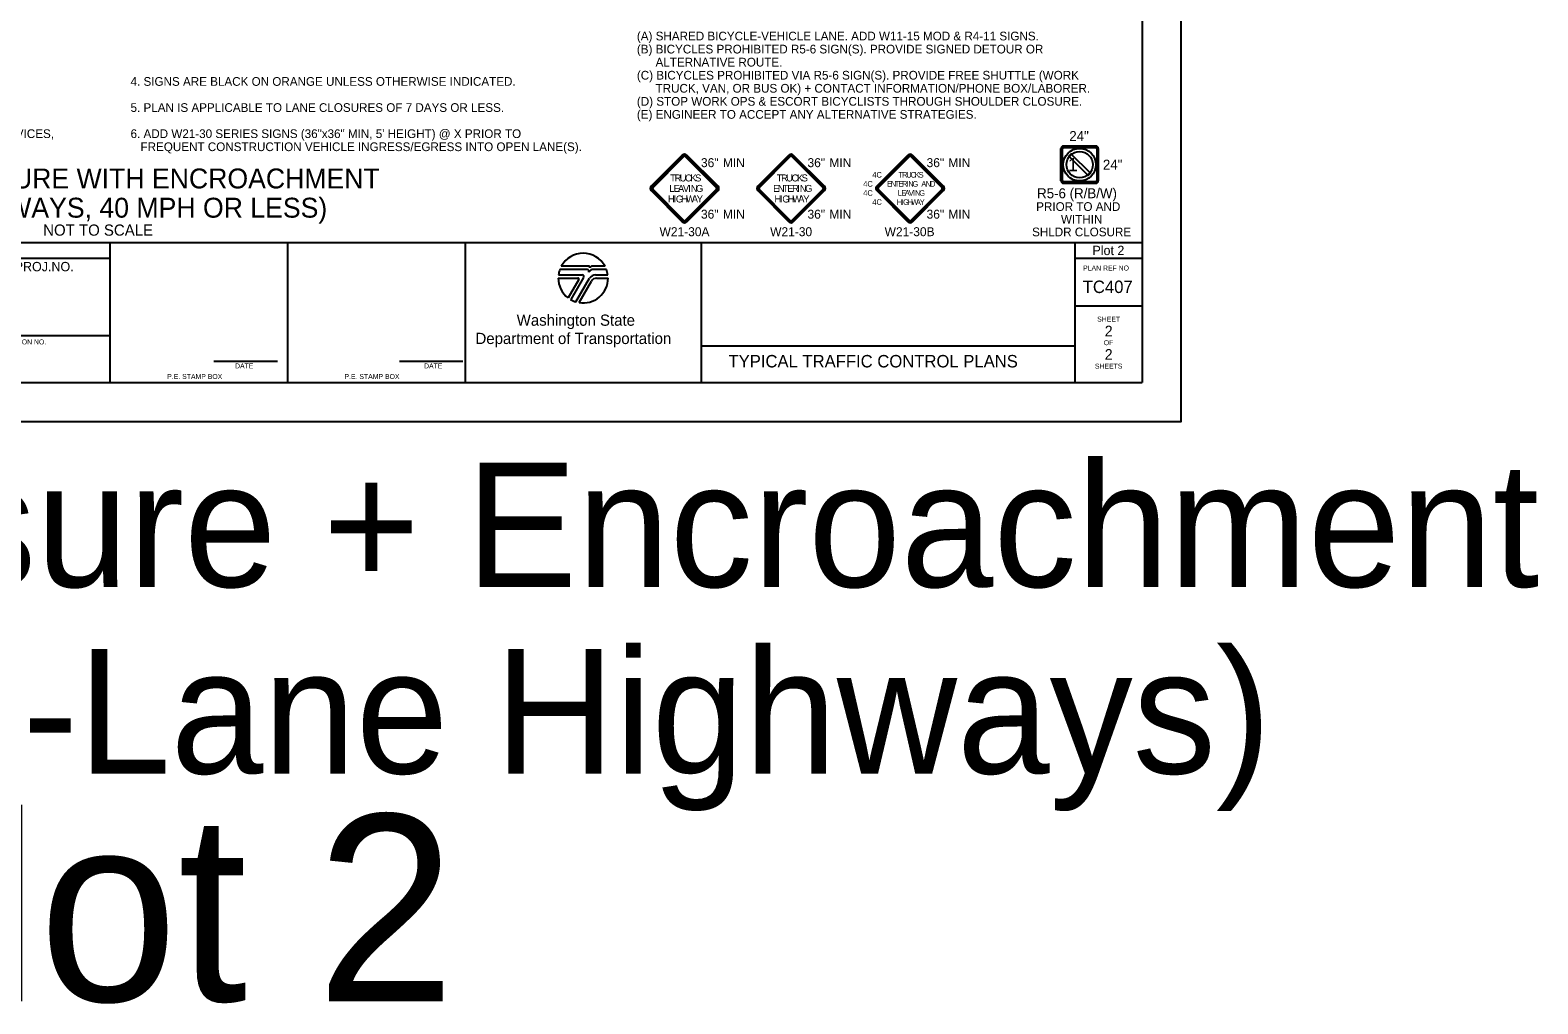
# Model space of a CAD drawing. Extents: x 99999.1 to 100096.1, y 99995 to 100010.7.
# Drawn here: x 100026.81 to 100038.93, y 99995.01 to 100002.83 of the extents above; entities that cross this region are included whole.
import ezdxf

# ---------------------------------------------------------------- set-up
doc = ezdxf.new("R2010")
doc.units = 0
for name, color, linetype in [('SH_DE_DetailHeading1Text', 7, 'Continuous'), ('SH_GI_GeneralNotesBodyText', 7, 'Continuous'), ('SH_GI_PlotLimits', 7, 'Continuous'), ('SH_GI_SheetBorder', 7, 'Continuous'), ('SH_GI_SheetLocationText', 7, 'Continuous'), ('SH_GI_SheetTextInCells', 7, 'Continuous'), ('SH_GI_TitleBlockText', 7, 'Continuous'), ('SH_GI_WSDOTLogo', 7, 'Continuous'), ('TR_SN_ConstructionSigns', 7, 'Continuous')]:
    doc.layers.add(name, color=color, linetype=linetype)

msp = doc.modelspace()

# ---------------------------------------------------------------- linework, layer by layer
at = {"layer": 'SH_GI_PlotLimits'}
msp.add_lwpolyline([(100019.062, 99999.687), (100036.062, 99999.687), (100036.062, 100010.687), (100019.062, 100010.687)], close=True, dxfattribs=at)
at = {"layer": 'SH_GI_SheetBorder'}
for p, q in [((100035.75, 100010.375), (100035.75, 100000)), ((100020, 100001.126), (100035.75, 100001.126)), ((100027.457, 100000), (100027.457, 100001.126)), ((100028.883, 100000), (100028.883, 100001.126)), ((100030.309, 100001.126), (100030.309, 100000)), ((100032.205, 100001.126), (100032.205, 100000)), ((100035.208, 100001.126), (100035.208, 100000)), ((100020, 100001.001), (100027.457, 100001.001)), ((100035.208, 100001.001), (100035.75, 100001.001)), ((100035.208, 100000.618), (100035.75, 100000.618)), ((100027.457, 100000.375), (100025.447, 100000.375)), ((100032.205, 100000.295), (100035.208, 100000.295)), ((100028.29, 100000.173), (100028.802, 100000.173)), ((100029.78, 100000.173), (100030.291, 100000.173)), ((100020, 100000), (100035.75, 100000))]:
    msp.add_line(p, q, dxfattribs=at)
at = {"layer": 'SH_GI_WSDOTLogo'}
for p, q in [((100031.303, 100000.935), (100031.081, 100000.935)), ((100031.433, 100000.935), (100031.335, 100000.935)), ((100031.057, 100000.84), (100031.215, 100000.84)), ((100031.059, 100000.866), (100031.25, 100000.866)), ((100031.289, 100000.909), (100031.07, 100000.909)), ((100031.222, 100000.828), (100031.136, 100000.681)), ((100031.261, 100000.846), (100031.157, 100000.667)), ((100031.199, 100000.649), (100031.309, 100000.839)), ((100031.224, 100000.643), (100031.324, 100000.816)), ((100031.445, 100000.909), (100031.343, 100000.909)), ((100031.343, 100000.909), (100031.343, 100000.909)), ((100031.356, 100000.866), (100031.456, 100000.866)), ((100031.365, 100000.839), (100031.457, 100000.839))]:
    msp.add_line(p, q, dxfattribs=at)
for centre, radius, start, end in [((100031.257, 100000.84), 0.2, 28.4787, 151.532), ((100031.303, 100000.926), 0.00903, 329.8742, 90.0033), ((100031.335, 100000.907), 0.0287, 90.0072, 148.1676), ((100031.257, 100000.84), 0.2, 179.9986, 232.8433), ((100031.257, 100000.84), 0.2, 159.696, 172.5057), ((100031.215, 100000.832), 0.0082, 329.7436, 90), ((100031.257, 100000.84), 0.2, 260.5455, 359.8086), ((100031.25, 100000.853), 0.0131, 329.7683, 90), ((100031.289, 100000.895), 0.0148, 327.8418, 89.9985), ((100031.343, 100000.861), 0.0484, 89.9953, 147.8238), ((100031.356, 100000.812), 0.0542, 90, 149.9974), ((100031.365, 100000.792), 0.0476, 90, 150.0543), ((100031.257, 100000.84), 0.2, 7.4943, 20.2941), ((100031.257, 100000.84), 0.2, 239.7929, 253.0448)]:
    msp.add_arc(centre, radius, start, end, dxfattribs=at)
at = {"layer": 'TR_SN_ConstructionSigns'}
for p, q in [((100032.054, 100001.829), (100031.804, 100001.579)), ((100032.059, 100001.824), (100031.809, 100001.574)), ((100031.816, 100001.567), (100032.066, 100001.817)), ((100032.078, 100001.817), (100032.329, 100001.567)), ((100032.336, 100001.574), (100032.085, 100001.824)), ((100032.341, 100001.579), (100032.09, 100001.829)), ((100032.91, 100001.829), (100032.66, 100001.579)), ((100032.915, 100001.824), (100032.665, 100001.574)), ((100032.672, 100001.567), (100032.922, 100001.817)), ((100032.934, 100001.817), (100033.185, 100001.567)), ((100033.192, 100001.574), (100032.941, 100001.824)), ((100033.197, 100001.579), (100032.946, 100001.829)), ((100033.867, 100001.829), (100033.616, 100001.579)), ((100033.872, 100001.824), (100033.621, 100001.574)), ((100033.628, 100001.567), (100033.879, 100001.817)), ((100033.891, 100001.817), (100034.141, 100001.567)), ((100034.148, 100001.574), (100033.898, 100001.824)), ((100034.153, 100001.579), (100033.903, 100001.829)), ((100035.097, 100001.883), (100035.097, 100001.621)), ((100035.097, 100001.621), (100035.097, 100001.883)), ((100035.097, 100001.883), (100035.097, 100001.621)), ((100035.102, 100001.883), (100035.102, 100001.621)), ((100035.11, 100001.621), (100035.11, 100001.883)), ((100035.378, 100001.902), (100035.116, 100001.902)), ((100035.116, 100001.902), (100035.378, 100001.902)), ((100035.378, 100001.902), (100035.116, 100001.902)), ((100035.378, 100001.897), (100035.116, 100001.897)), ((100035.116, 100001.889), (100035.378, 100001.889)), ((100035.385, 100001.883), (100035.385, 100001.621)), ((100035.392, 100001.621), (100035.392, 100001.883)), ((100035.397, 100001.621), (100035.397, 100001.883)), ((100035.397, 100001.883), (100035.397, 100001.621)), ((100035.397, 100001.621), (100035.397, 100001.883)), ((100031.804, 100001.543), (100032.054, 100001.292)), ((100031.809, 100001.548), (100032.059, 100001.297)), ((100032.066, 100001.304), (100031.816, 100001.555)), ((100032.329, 100001.555), (100032.078, 100001.304)), ((100032.085, 100001.297), (100032.336, 100001.548)), ((100032.09, 100001.292), (100032.341, 100001.543)), ((100032.66, 100001.543), (100032.91, 100001.292)), ((100032.665, 100001.548), (100032.915, 100001.297)), ((100032.922, 100001.304), (100032.672, 100001.555)), ((100033.185, 100001.555), (100032.934, 100001.304)), ((100032.941, 100001.297), (100033.192, 100001.548)), ((100032.946, 100001.292), (100033.197, 100001.543)), ((100033.616, 100001.543), (100033.867, 100001.292)), ((100033.621, 100001.548), (100033.872, 100001.297)), ((100033.879, 100001.304), (100033.628, 100001.555)), ((100034.141, 100001.555), (100033.891, 100001.304)), ((100033.898, 100001.297), (100034.148, 100001.548)), ((100033.903, 100001.292), (100034.153, 100001.543)), ((100035.378, 100001.614), (100035.116, 100001.614)), ((100035.116, 100001.607), (100035.378, 100001.607)), ((100035.116, 100001.602), (100035.378, 100001.602)), ((100035.378, 100001.602), (100035.116, 100001.602)), ((100035.116, 100001.602), (100035.378, 100001.602))]:
    msp.add_line(p, q, dxfattribs=at)
msp.add_lwpolyline([(100035.331, 100001.686), (100035.181, 100001.835), (100035.178, 100001.839), (100035.16, 100001.821), (100035.313, 100001.668), (100035.316, 100001.665), (100035.334, 100001.683), (100035.331, 100001.686)], dxfattribs=at)
for radius in [0.131, 0.106]:
    msp.add_circle((100035.247, 100001.752), radius, dxfattribs=at)
for centre, radius, start, end in [((100032.072, 100001.811), 0.0253, 45, 135), ((100032.072, 100001.811), 0.0183, 45, 135), ((100032.072, 100001.811), 0.00844, 45, 135), ((100032.928, 100001.811), 0.0253, 45, 135), ((100032.928, 100001.811), 0.0183, 45, 135), ((100032.928, 100001.811), 0.00844, 45, 135), ((100033.885, 100001.811), 0.0253, 45, 135), ((100033.885, 100001.811), 0.0183, 45, 135), ((100033.885, 100001.811), 0.00844, 45, 135), ((100035.116, 100001.883), 0.0187, 90, 180), ((100035.116, 100001.883), 0.0187, 90, 180), ((100035.116, 100001.883), 0.0187, 90, 180), ((100035.116, 100001.883), 0.0141, 90, 180), ((100035.116, 100001.883), 0.00625, 90, 180), ((100035.378, 100001.883), 0.0187, 0, 90), ((100035.378, 100001.883), 0.0187, 0, 90), ((100035.378, 100001.883), 0.0187, 0, 90), ((100035.378, 100001.883), 0.0141, 0, 90), ((100035.378, 100001.883), 0.00625, 0, 90), ((100031.822, 100001.561), 0.0253, 135, 225), ((100031.822, 100001.561), 0.0183, 135, 225), ((100031.822, 100001.561), 0.00844, 135, 225), ((100032.323, 100001.561), 0.00844, 315, 45), ((100032.323, 100001.561), 0.0183, 315, 45), ((100032.323, 100001.561), 0.0253, 315, 45), ((100032.678, 100001.561), 0.0253, 135, 225), ((100032.678, 100001.561), 0.0183, 135, 225), ((100032.678, 100001.561), 0.00844, 135, 225), ((100033.179, 100001.561), 0.00844, 315, 45), ((100033.179, 100001.561), 0.0183, 315, 45), ((100033.179, 100001.561), 0.0253, 315, 45), ((100033.634, 100001.561), 0.0253, 135, 225), ((100033.634, 100001.561), 0.0183, 135, 225), ((100033.634, 100001.561), 0.00844, 135, 225), ((100034.135, 100001.561), 0.00844, 315, 45), ((100034.135, 100001.561), 0.0183, 315, 45), ((100034.135, 100001.561), 0.0253, 315, 45), ((100035.116, 100001.621), 0.0187, 180, 270), ((100035.116, 100001.621), 0.0187, 180, 270), ((100035.116, 100001.621), 0.0187, 180, 270), ((100035.116, 100001.621), 0.0141, 180, 270), ((100035.116, 100001.621), 0.00625, 180, 270), ((100035.378, 100001.621), 0.0141, 270, 0), ((100035.378, 100001.621), 0.00625, 270, 0), ((100035.378, 100001.621), 0.0187, 270, 0), ((100035.378, 100001.621), 0.0187, 270, 0), ((100035.378, 100001.621), 0.0187, 270, 0), ((100032.072, 100001.31), 0.00844, 225, 315), ((100032.928, 100001.31), 0.00844, 225, 315), ((100033.885, 100001.31), 0.00844, 225, 315), ((100032.072, 100001.31), 0.0253, 225, 315), ((100032.072, 100001.31), 0.0183, 225, 315), ((100032.928, 100001.31), 0.0253, 225, 315), ((100032.928, 100001.31), 0.0183, 225, 315), ((100033.885, 100001.31), 0.0253, 225, 315), ((100033.885, 100001.31), 0.0183, 225, 315)]:
    msp.add_arc(centre, radius, start, end, dxfattribs=at)

# ---------------------------------------------------------------- texts
at = {"layer": 'SH_DE_DetailHeading1Text'}
for s, height, p in [('SHOULDER CLOSURE WITH ENCROACHMENT', 0.16, (100024.844, 100001.561)), ('(4-LANE HIGHWAYS, 40 MPH OR LESS)', 0.16, (100025.206, 100001.326)), ('NOT TO SCALE', 0.09, (100026.918, 100001.181))]:
    msp.add_text(s, height=height, rotation=360, dxfattribs=at).set_placement(p)
at = {"layer": 'SH_GI_GeneralNotesBodyText'}
for s, p in [('(A) SHARED BICYCLE-VEHICLE LANE. ADD W11-15 MOD & R4-11 SIGNS.', (100031.689, 100002.751)), ('(B) BICYCLES PROHIBITED R5-6 SIGN(S). PROVIDE SIGNED DETOUR OR ', (100031.689, 100002.646)), ('(C) BICYCLES PROHIBITED VIA R5-6 SIGN(S). PROVIDE FREE SHUTTLE (WORK ', (100031.689, 100002.436)), ('ALTERNATIVE ROUTE.', (100031.839, 100002.541)), ('4. SIGNS ARE BLACK ON ORANGE UNLESS OTHERWISE INDICATED.', (100027.62, 100002.386)), ('TRUCK, VAN, OR BUS OK) + CONTACT INFORMATION/PHONE BOX/LABORER. ', (100031.839, 100002.331)), ('(D) STOP WORK OPS & ESCORT BICYCLISTS THROUGH SHOULDER CLOSURE.', (100031.689, 100002.226)), ('5. PLAN IS APPLICABLE TO LANE CLOSURES OF 7 DAYS OR LESS.', (100027.62, 100002.176)), ('(E) ENGINEER TO ACCEPT ANY ALTERNATIVE STRATEGIES.', (100031.689, 100002.121)), ('3. 28" TRAFFIC CONES, 36" TRAFFIC CONES, 42" TALL CHANNELIZING DEVICES, ', (100023.389, 100001.966)), ('6. ADD W21-30 SERIES SIGNS (36"x36" MIN, 5\' HEIGHT) @ X PRIOR TO ', (100027.62, 100001.966)), ('FREQUENT CONSTRUCTION VEHICLE INGRESS/EGRESS INTO OPEN LANE(S).', (100027.7, 100001.861))]:
    msp.add_text(s, height=0.07, rotation=360, dxfattribs=at).set_placement(p)
at = {"layer": 'SH_GI_SheetBorder'}
msp.add_text('PLAN REF NO', height=0.04003, dxfattribs=at).set_placement((100035.275, 100000.901))
at = {"layer": 'SH_GI_SheetLocationText'}
for s, height, p in [('Plot 2', 0.075, (100035.35, 100001.025)), ('Shoulder Closure + Encroachment', 1, (100018.461, 99998.357)), ('(45+ mph 4-Lane Highways)', 1, (100019.952, 99996.857)), ('Plot 2', 1.5, (100025.1, 99995.027))]:
    msp.add_text(s, height=height, dxfattribs=at).set_placement(p)
at = {"layer": 'SH_GI_SheetTextInCells'}
for s, height, p in [('FED.AID PROJ.NO.', 0.07506, (100026.265, 100000.895)), ('Washington State', 0.09007, (100030.723, 100000.457)), ('SHEET', 0.04, (100035.388, 100000.49)), ('LOCATION NO.', 0.04003, (100026.546, 100000.307)), ('Department of Transportation', 0.09007, (100030.392, 100000.31)), ('OF', 0.04, (100035.441, 100000.301)), ('DATE', 0.04, (100028.46, 100000.114)), ('DATE', 0.04, (100029.979, 100000.114)), ('SHEETS', 0.04, (100035.37, 100000.112)), ('P.E. STAMP BOX', 0.04003, (100027.915, 100000.029)), ('P.E. STAMP BOX', 0.04003, (100029.339, 100000.029))]:
    msp.add_text(s, height=height, dxfattribs=at).set_placement(p)
at = {"layer": 'SH_GI_TitleBlockText'}
for s, height, p in [('TC407', 0.1, (100035.272, 100000.72)), ('2', 0.085, (100035.449, 100000.372)), ('TYPICAL TRAFFIC CONTROL PLANS', 0.1, (100032.425, 100000.122)), ('2', 0.085, (100035.449, 100000.184))]:
    msp.add_text(s, height=height, dxfattribs=at).set_placement(p)
at = {"layer": 'TR_SN_ConstructionSigns'}
for s, height, p in [('24"', 0.08, (100035.164, 100001.942)), ('36"', 0.072, (100032.204, 100001.732)), ('MIN', 0.072, (100032.38, 100001.732)), ('36"', 0.072, (100033.06, 100001.732)), ('MIN', 0.072, (100033.236, 100001.732)), ('36"', 0.072, (100034.017, 100001.732)), ('MIN', 0.072, (100034.192, 100001.732)), ('24"', 0.08, (100035.434, 100001.712)), ('R5-6 (R/B/W)', 0.08, (100034.905, 100001.482)), ('PRIOR TO AND', 0.07, (100034.898, 100001.38)), ('36"', 0.072, (100032.204, 100001.318)), ('MIN', 0.072, (100032.38, 100001.318)), ('36"', 0.072, (100033.06, 100001.318)), ('MIN', 0.072, (100033.236, 100001.318)), ('36"', 0.072, (100034.017, 100001.318)), ('MIN', 0.072, (100034.192, 100001.318)), ('WITHIN', 0.07, (100035.097, 100001.278)), ('W21-30A', 0.072, (100031.871, 100001.177)), ('W21-30', 0.072, (100032.76, 100001.177)), ('W21-30B', 0.072, (100033.68, 100001.177)), ('SHLDR CLOSURE', 0.07, (100034.865, 100001.176))]:
    msp.add_text(s, height=height, rotation=360, dxfattribs=at).set_placement(p)
for s, height, p in [('1', 0.106, (100035.154, 100001.699)), ('T', 0.0562, (100031.956, 100001.617)), ('R', 0.0562, (100031.992, 100001.617)), ('U', 0.0562, (100032.033, 100001.617)), ('C', 0.0562, (100032.076, 100001.617)), ('K', 0.0562, (100032.119, 100001.617)), ('S', 0.0562, (100032.157, 100001.617)), ('T', 0.0562, (100032.812, 100001.617)), ('R', 0.0562, (100032.848, 100001.617)), ('U', 0.0562, (100032.889, 100001.617)), ('C', 0.0562, (100032.932, 100001.617)), ('K', 0.0562, (100032.975, 100001.617)), ('S', 0.0562, (100033.013, 100001.617)), ('4C', 0.045, (100033.581, 100001.648)), ('T', 0.045, (100033.791, 100001.648)), ('R', 0.045, (100033.821, 100001.648)), ('U', 0.045, (100033.854, 100001.648)), ('C', 0.045, (100033.888, 100001.648)), ('K', 0.045, (100033.922, 100001.648)), ('S', 0.045, (100033.953, 100001.648)), ('L', 0.0562, (100031.949, 100001.533)), ('E', 0.0562, (100031.985, 100001.533)), ('A', 0.0562, (100032.019, 100001.533)), ('V', 0.0562, (100032.059, 100001.533)), ('I', 0.0562, (100032.101, 100001.533)), ('N', 0.0562, (100032.122, 100001.533)), ('G', 0.0562, (100032.164, 100001.533)), ('E', 0.0562, (100032.784, 100001.533)), ('N', 0.0562, (100032.822, 100001.533)), ('T', 0.0562, (100032.862, 100001.533)), ('E', 0.0562, (100032.898, 100001.533)), ('R', 0.0562, (100032.937, 100001.533)), ('I', 0.0562, (100032.978, 100001.533)), ('N', 0.0562, (100032.998, 100001.533)), ('G', 0.0562, (100033.041, 100001.533)), ('4C', 0.045, (100033.508, 100001.575)), ('4C', 0.045, (100033.508, 100001.502)), ('E', 0.045, (100033.699, 100001.575)), ('N', 0.045, (100033.73, 100001.575)), ('T', 0.045, (100033.761, 100001.575)), ('L', 0.045, (100033.786, 100001.502)), ('E', 0.045, (100033.791, 100001.575)), ('E', 0.045, (100033.815, 100001.502)), ('R', 0.045, (100033.821, 100001.575)), ('A', 0.045, (100033.842, 100001.502)), ('I', 0.045, (100033.854, 100001.575)), ('V', 0.045, (100033.874, 100001.502)), ('N', 0.045, (100033.87, 100001.575)), ('G', 0.045, (100033.904, 100001.575)), ('I', 0.045, (100033.908, 100001.502)), ('N', 0.045, (100033.924, 100001.502)), ('G', 0.045, (100033.958, 100001.502)), ('A', 0.045, (100033.975, 100001.575)), ('N', 0.045, (100034.01, 100001.575)), ('D', 0.045, (100034.045, 100001.575)), ('H', 0.0562, (100031.939, 100001.448)), ('I', 0.0562, (100031.983, 100001.448)), ('G', 0.0562, (100032.002, 100001.448)), ('H', 0.0562, (100032.045, 100001.448)), ('W', 0.0562, (100032.084, 100001.448)), ('A', 0.0562, (100032.13, 100001.448)), ('Y', 0.0562, (100032.17, 100001.448)), ('H', 0.0562, (100032.795, 100001.448)), ('I', 0.0562, (100032.839, 100001.448)), ('G', 0.0562, (100032.858, 100001.448)), ('H', 0.0562, (100032.901, 100001.448)), ('W', 0.0562, (100032.94, 100001.448)), ('A', 0.0562, (100032.986, 100001.448)), ('Y', 0.0562, (100033.026, 100001.448)), ('4C', 0.045, (100033.581, 100001.429)), ('H', 0.045, (100033.778, 100001.429)), ('I', 0.045, (100033.813, 100001.429)), ('G', 0.045, (100033.828, 100001.429)), ('H', 0.045, (100033.863, 100001.429)), ('W', 0.045, (100033.894, 100001.429)), ('A', 0.045, (100033.931, 100001.429)), ('Y', 0.045, (100033.962, 100001.429))]:
    msp.add_text(s, height=height, dxfattribs=at).set_placement(p)

doc.saveas('drawing.dxf')
